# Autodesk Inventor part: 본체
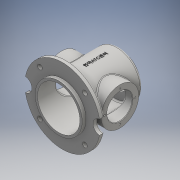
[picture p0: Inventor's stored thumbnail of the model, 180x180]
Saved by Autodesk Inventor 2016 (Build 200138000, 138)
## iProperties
Created: 2018-04
Part Number: 본체
Material: 일반
Document SubType Name: Modeling
Designer: 605-06
Density: 1 g/cm^3
Appearance: 기본값
Author: 605-06
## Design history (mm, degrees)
sketch "스케치1"
  geometry: C1 r 80 at (0, 0); 1 further point
  constraints: 1 centre point, 1 coincident
  dimensions: "d0" = 160 diameter of C1
extrude "돌출1" new body sketch "스케치1" distance "d1" = 10; taper "d2" = 0 deg
sketch "스케치2"
  geometry: C1 r 50 at (0, 0); 1 further point
  constraints: 1 centre point, 1 coincident
  dimensions: "d3" = 100 diameter of C1
extrude "돌출2" join sketch "스케치2" distance "d4" = 110; taper "d6" = 0 deg; dims "d5" = 18, "d7" = 0
sketch "스케치3"
  geometry: C1 r 40 at (0, 0); 1 further point
  constraints: 1 centre point, 1 coincident
  dimensions: "d8" = 80 diameter of C1
extrude "돌출3" join sketch "스케치3" distance "d9" = 5; taper "d10" = 0 deg
sketch "스케치4"
  geometry: C1 r 15 at (-80, 0); C2 r 15 at (80, 0); A1 r 80 centre (0, 0) between (-80, 0) and (80, 0) reference; 1 further point
  constraints: 2 centre point, 2 horizontal alignment, 2 point on circle
  dimensions: "d11" = 30 diameter of C1; "d12" = 30 diameter of C2
extrude "돌출4" cut sketch "스케치4" stored distance "d13" = 0; taper "d14" = 0 deg
sketch "스케치5"
  geometry: C1 r 40 at (60, 0); 1 further point
  constraints: 1 centre point, 1 horizontal alignment
  dimensions: "d15" = 80 diameter of C1; "d16" = 60 distance of C1.centre point (0, 0)
extrude "돌출5" join sketch "스케치5" stored distance "d17" = 124; taper "d18" = 0 deg
sketch "스케치6"
  geometry: C1 r 45 at (0, 0); 1 further point
  constraints: 1 centre point, 1 coincident
  dimensions: "d19" = 90 diameter of C1
extrude "돌출6" cut sketch "스케치6" distance "d20" = 120; taper "d21" = 0 deg
sketch "스케치7"
  geometry: C1 r 27 at (0, 0); 1 further point
  constraints: 1 centre point, 1 coincident
  dimensions: "d22" = 54 diameter of C1
extrude "돌출7" cut sketch "스케치7" stored distance "d23" = 120; taper "d24" = 0 deg
sketch "스케치8"
  geometry: C1 r 27 at (0, 0); C2 r 40 at (0, 0) reference; 1 further point
  constraints: 1 centre point, 1 concentric
  dimensions: "d25" = 54 diameter of C1
extrude "돌출8" cut sketch "스케치8" stored distance "d26" = 0; taper "d27" = 0 deg
sketch "스케치9"
  geometry: L1 (0, 67.5)-(0, -67.5); L2 (-47.73, 47.73)-(47.73, -47.73); L3 (-67.5, 0)-(67.5, 0); L4 (-47.73, -47.73)-(47.73, 47.73); L5 (0, -67.5)-(0, 67.5); L6 (47.73, -47.73)-(-47.73, 47.73); L7 (67.5, 0)-(-67.5, 0); L8 (47.73, 47.73)-(-47.73, -47.73); A1 r 67.5 centre (0, 0) between (0, 67.5) and (0, -67.5); 20 further points
  constraints: 16 end point, 9 midpoint, 5 coincident, 2 point on circle, 1 centre point, 1 vertical, 41 other
  dimensions: "d28" = 135 diameter of A1; "d31" = 360 deg dimension on A1.centre L1.start (derived)
hole "구멍1" sketch "스케치9" at (-47.73, 47.73), (47.73, 47.73), (47.73, -47.73), (-47.73, -47.73) diameter "d33" = 10; stored, may be unused: countersink angle "d37" = 90 deg, drill point angle "d39" = 118 deg; dims "d34" = 6, "d35" = 4, "d36" = 2, "d38" = 8
sketch "스케치10"
  geometry: C1 r 40 at (0, 0) reference; A1 r 32.5 centre (0, 0) between (0, 32.5) and (-32.5, 0); 3 further points
  constraints: 4 point on circle, 2 horizontal alignment, 2 vertical alignment, 1 centre point, 1 concentric
  dimensions: "d40" = 65 diameter of A1
hole "구멍2" sketch "스케치10" at (0, 32.5), (-32.5, 0), (0, -32.5), (32.5, 0) diameter "d41" = 3.459; stored, may be unused: countersink angle "d45" = 90 deg, drill point angle "d47" = 118 deg; dims "d42" = 8, "d43" = 4, "d44" = 2, "d46" = 10
sketch "스케치11"
  geometry: A1 r 32.5 centre (0, 0) between (32.5, 0) and (0, 32.5); 3 further points
  constraints: 4 point on circle, 2 horizontal alignment, 2 vertical alignment, 1 centre point, 1 coincident
  dimensions: "d48" = 65 diameter of A1
hole "구멍3" sketch "스케치11" at (0, 32.5), (-32.5, 0), (0, -32.5), (32.5, 0) diameter "d49" = 3.459; stored, may be unused: countersink angle "d53" = 90 deg, drill point angle "d55" = 118 deg; dims "d50" = 8, "d51" = 4, "d52" = 2, "d54" = 10
fillet "모깎기1" dims "d56" = 5
fillet "모깎기2" dims "d57" = 3
chamfer "모따기1" distance "d58" = 1; stored, may be unused: second distance "d59" = 2, angle "d60" = 45 deg
node "작업 평면1"
sketch "스케치12"
  geometry: L1 (9.52, 45.551)-(9.52, 95.326); L2 (9.52, 95.326)-(-10.221, 95.326); L3 (-10.221, 95.326)-(-10.221, 45.551); L4 (-10.221, 45.551)-(9.52, 45.551); L5 (0, 0)-(0, 70)
  constraints: 2 end point, 1 vertical, 2 other
  dimensions: "d62" = 70 distance of L5.start L5.end
feature "엠보싱1" sketch "스케치12" dims "d63" = 0.5, "d64" = 0
fillet "모깎기3" dims "d68" = 3
node "솔리드1"
mirror "대칭1"
other parameters: "d61" = 105.25
